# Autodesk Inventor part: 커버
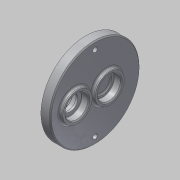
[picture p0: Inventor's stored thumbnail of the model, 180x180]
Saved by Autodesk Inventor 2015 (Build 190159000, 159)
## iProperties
Created: 2016-02
Part Number: 커버
Material: 알루미늄 6061
Document SubType Name: Modeling
Designer: mduedu
Density: 2.71 g/cm^3
Appearance: Aluminum - Flat
Mass: 137.934 g
Surface Area: 159.866 cm^2
Volume: 50.898 cm^3
Author: mduedu
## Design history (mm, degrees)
sketch "스케치1"
  geometry: C1 r 43 at (0, 0); 1 further point
  constraints: 1 centre point, 1 coincident
  dimensions: "d0" = 86 diameter of C1
extrude "돌출1" new body sketch "스케치1" distance "d1" = 9; taper "d2" = 0 deg
sketch "스케치2"
  geometry: C1 r 14 at (0, 11); 1 further point
  constraints: 1 centre point, 1 vertical alignment
  dimensions: "d3" = 28 diameter of C1; "d6" = 11 distance of C1.centre point (0, 0)
extrude "돌출2" join sketch "스케치2" distance "d7" = 3; taper "d8" = 0 deg
sketch "스케치3"
  geometry: C1 r 14 at (0, -20); 1 further point
  constraints: 1 centre point, 1 vertical alignment
  dimensions: "d9" = 28 diameter of C1; "d10" = 20 distance of C1.centre point (0, 0)
extrude "돌출3" join sketch "스케치3" distance "d11" = 3; taper "d12" = 0 deg
hole "구멍1" diameter "d15" = 22; stored, may be unused: countersink angle "d19" = 90 deg, drill point angle "d21" = 0 deg; dims "d13" = 10, "d14" = 10, "d16" = 6, "d17" = 4, "d18" = 2, "d20" = 7
hole "구멍2" diameter "d24" = 18; stored, may be unused: countersink angle "d28" = 90 deg, drill point angle "d30" = 0 deg; dims "d22" = 10, "d23" = 10, "d25" = 6, "d26" = 4, "d27" = 2, "d29" = 1
hole "구멍3" diameter "d33" = 22; stored, may be unused: countersink angle "d37" = 90 deg, drill point angle "d39" = 0 deg; dims "d34" = 6, "d35" = 4, "d36" = 2, "d38" = 7, "d73" = 10, "d74" = 10
sketch "스케치4"
  geometry: C1 r 14 at (0, -20) reference; C2 r 18 at (0, -20); 1 further point
  constraints: 1 centre point, 1 coincident
  dimensions: "d40" = 36 diameter of C2
extrude "돌출4" join sketch "스케치4" distance "d41" = 4; taper "d42" = 0 deg
hole "구멍4" diameter "d45" = 22; stored, may be unused: countersink angle "d49" = 90 deg, drill point angle "d51" = 0 deg; dims "d43" = 10, "d44" = 10, "d46" = 6, "d47" = 4, "d48" = 2, "d50" = 7
hole "구멍5" diameter "d54" = 15; stored, may be unused: countersink angle "d58" = 90 deg, drill point angle "d60" = 0 deg; dims "d52" = 10, "d53" = 10, "d55" = 6, "d56" = 4, "d57" = 2, "d59" = 7
fillet "모깎기1" dims "d61" = 0.3
fillet "모깎기2" dims "d62" = 2
chamfer "모따기1" distance "d63" = 1; stored, may be unused: second distance "d64" = 2, angle "d65" = 45 deg
fillet "모깎기6" dims "d88" = 2
sketch "스케치5" dims "d67" = 72
  geometry: 4 further points
  constraints: 2 horizontal alignment, 1 coincident, 5 other
  dimensions: "d71" = 360 deg dimension on point (0, 0) point (-36, 0) (derived)
fillet "모깎기4" dims "d75" = 2
sketch "스케치6"
  geometry: 2 further points
hole "구멍6" sketch "스케치6" at (36, 0), (-36, 0) diameter "d76" = 4.5; stored, may be unused: countersink angle "d80" = 90 deg, drill point angle "d82" = 0 deg; dims "d77" = 6, "d78" = 8, "d79" = 4.6, "d81" = 8
chamfer "모따기2" distance "d90" = 1; stored, may be unused: second distance "d91" = 2, angle "d92" = 45 deg
node "솔리드1"
